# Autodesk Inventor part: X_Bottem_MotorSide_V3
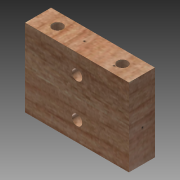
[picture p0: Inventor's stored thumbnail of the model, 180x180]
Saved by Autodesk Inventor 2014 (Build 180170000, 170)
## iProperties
Created: 2013-12
Part Number: X_Bottem_MotorSide_V3
Material: Birch
Document SubType Name: Modeling
Designer: Bram
Density: 0.512 g/cm^3
Appearance: Birch - Natural Medium Gloss
Author: Bram
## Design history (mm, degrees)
sketch "Sketch1"
  geometry: L1 (0, 0)-(80, 0); L2 (80, 0)-(80, 60); L3 (80, 60)-(0, 60); L4 (0, 60)-(0, 0); C1 r 4 at (40, 45); C2 r 4 at (40, 15)
  constraints: 8 end point, 2 centre point, 2 parallel, 1 horizontal, 1 perpendicular
  dimensions: "d0" = 80 distance of L3.end L2.end; "d1" = 60 distance of L2.end L1.end; "d4" = 8 diameter of C1; "d5" = 8 diameter of C2
extrude "Extrusion1" new body sketch "Sketch1" distance "d6" = 20; taper "d7" = 0 deg
sketch "Sketch2"
  geometry: C1 r 4 at (15, 10); C2 r 4 at (65, 10)
  constraints: 2 centre point
  dimensions: "d10" = 8 diameter of C1; "d11" = 8 diameter of C2
extrude "Extrusion2" cut sketch "Sketch2" distance "d12" = 60; taper "d13" = 0 deg
body "Solid1"
